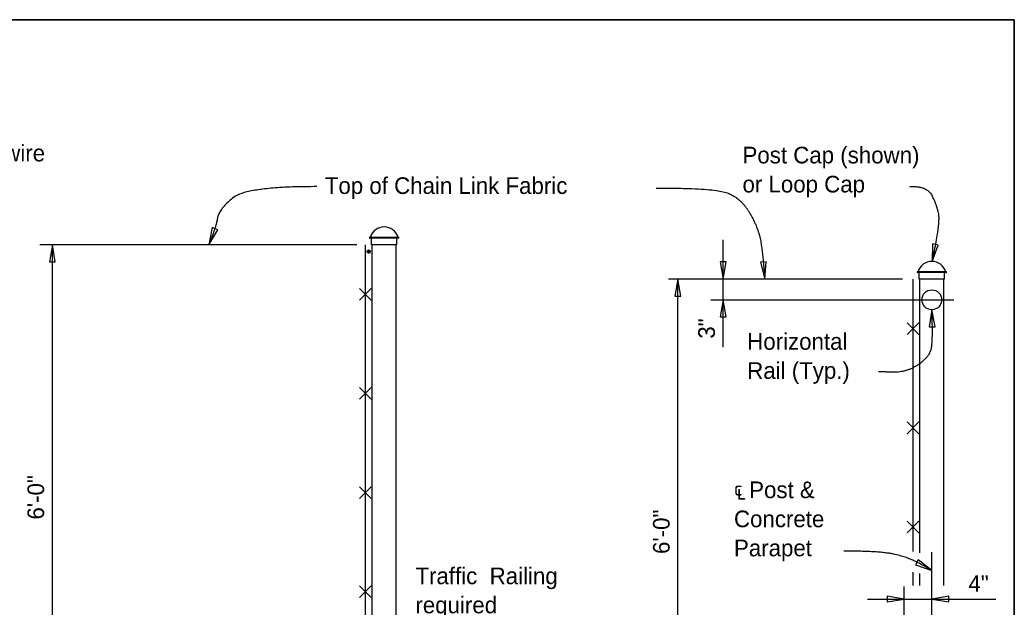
# Model space of a CAD drawing. Extents: x 0 to 41.1, y 0 to 25.9.
# Drawn here: x 29.01 to 41.05, y 18.84 to 25.95 of the extents above; entities that cross this region are included whole.
import ezdxf

# ---------------------------------------------------------------- set-up
doc = ezdxf.new("R2010")
doc.units = 0
for name, color, linetype in [('ActivePts-ConstElements', 7, 'Continuous'), ('CL_Major', 7, 'Continuous'), ('Dimension', 7, 'Continuous'), ('Miscellaneous', 7, 'Continuous'), ('Miscellaneous1', 7, 'Continuous'), ('SteelMisc', 7, 'Continuous'), ('TextStructures', 7, 'Continuous')]:
    doc.layers.add(name, color=color, linetype=linetype)

msp = doc.modelspace()

# ---------------------------------------------------------------- linework, layer by layer
at = {"layer": 'ActivePts-ConstElements'}
msp.add_lwpolyline([(0, 0), (41.051, 0), (41.051, 25.946), (0, 25.946)], close=True, dxfattribs=at)
msp.add_lwpolyline([(0, 0), (41.051, 0), (41.051, 25.946), (0, 25.946)], close=True, dxfattribs=at)
msp.add_lwpolyline([(0, 0), (41.051, 0), (41.051, 25.946), (0, 25.946)], close=True, dxfattribs=at)
at = {"layer": 'CL_Major'}
for p, q in [((37.378, 22.558), (40.319, 22.558)), ((40.054, 15.283), (40.054, 19.502))]:
    msp.add_line(p, q, dxfattribs=at)
at = {"layer": 'Dimension'}
for p, q in [((37.528, 21.984), (37.528, 23.282)), ((33.092, 23.225), (29.256, 23.225)), ((29.406, 14.558), (29.406, 23.225)), ((39.699, 22.808), (36.866, 22.808)), ((36.98, 14.578), (36.98, 22.808)), ((39.72, 16.978), (39.72, 19.086)), ((39.274, 18.936), (40.828, 18.936))]:
    msp.add_line(p, q, dxfattribs=at)
for points in [[(31.3, 23.225), (31.408, 23.406), (31.342, 23.432)], [(40.057, 23.023), (40.131, 23.22), (40.062, 23.234)], [(29.406, 23.225), (29.371, 23.016), (29.441, 23.016)], [(37.528, 22.808), (37.563, 23.016), (37.492, 23.016)], [(38.031, 22.808), (38.049, 23.018), (37.979, 23.013)], [(36.98, 22.808), (36.944, 22.6), (37.015, 22.6)], [(37.528, 22.558), (37.492, 22.35), (37.563, 22.35)], [(40.054, 22.438), (40.024, 22.229), (40.095, 22.231)], [(40.054, 19.28), (39.889, 19.412), (39.855, 19.35)], [(39.72, 18.936), (39.512, 18.971), (39.512, 18.901)], [(40.054, 18.936), (40.262, 18.901), (40.262, 18.971)]]:
    msp.add_lwpolyline(points, close=True, dxfattribs=at)
for points in [[(32.608, 23.928), (31.76, 23.928), (31.424, 23.657), (31.383, 23.422), (31.3, 23.225)], [(36.717, 23.911), (37.4, 23.911), (37.736, 23.799), (37.958, 23.427), (38.014, 23.066), (38.031, 22.808)], [(39.786, 23.927), (39.992, 23.942), (40.118, 23.698), (40.152, 23.473), (40.057, 23.023)], [(39.41, 21.689), (39.436, 21.689), (39.754, 21.683), (40.017, 21.86), (40.072, 22.038), (40.054, 22.438)], [(38.988, 19.52), (39.396, 19.52), (39.727, 19.457), (39.975, 19.335), (40.054, 19.28)]]:
    msp.add_open_spline(points, degree=2, dxfattribs=at)
at = {"layer": 'Miscellaneous'}
for p, q in [((33.265, 22.695), (33.124, 22.554)), ((33.124, 22.695), (33.265, 22.554)), ((39.895, 22.279), (39.754, 22.137)), ((39.754, 22.279), (39.895, 22.137)), ((33.265, 21.495), (33.124, 21.354)), ((33.124, 21.495), (33.265, 21.354)), ((39.895, 21.079), (39.754, 20.937)), ((39.754, 21.079), (39.895, 20.937)), ((33.265, 20.295), (33.124, 20.154)), ((33.124, 20.295), (33.265, 20.154)), ((39.895, 19.879), (39.754, 19.737)), ((39.754, 19.879), (39.895, 19.737)), ((33.265, 19.095), (33.124, 18.954)), ((33.124, 19.095), (33.265, 18.954))]:
    msp.add_line(p, q, dxfattribs=at)
for points in [[(33.195, 23.225), (33.195, 17.225)], [(39.825, 22.808), (39.825, 19.51)], [(39.825, 19.262), (39.825, 19.1)]]:
    msp.add_lwpolyline(points, dxfattribs=at)
at = {"layer": 'Miscellaneous1'}
msp.add_lwpolyline([(0, 25.946), (41.051, 25.946), (41.051, 0), (0, 0)], close=True, dxfattribs=at)
at = {"layer": 'SteelMisc'}
for p, q in [((33.251, 23.317), (33.596, 23.317)), ((33.596, 23.304), (33.251, 23.304)), ((33.27, 23.225), (33.27, 23.304)), ((33.578, 23.225), (33.578, 23.304)), ((33.195, 23.225), (33.195, 17.225)), ((33.578, 23.225), (33.27, 23.225)), ((33.278, 16.889), (33.278, 23.225)), ((33.57, 16.889), (33.57, 23.225)), ((39.881, 22.9), (40.226, 22.9)), ((40.226, 22.888), (39.881, 22.888)), ((39.9, 22.808), (39.9, 22.888)), ((40.208, 22.808), (40.208, 22.888)), ((40.208, 22.808), (39.9, 22.808)), ((39.908, 19.495), (39.908, 22.808)), ((40.2, 19.1), (40.2, 22.808)), ((39.908, 19.1), (39.908, 19.244))]:
    msp.add_line(p, q, dxfattribs=at)
for centre, radius in [((33.236, 23.141), 0.0197), ((33.236, 23.141), 0.0172), ((33.236, 23.141), 0.0147), ((33.236, 23.141), 0.0122), ((33.236, 23.141), 0.00975), ((33.236, 23.141), 0.00725), ((33.236, 23.141), 0.00475), ((33.236, 23.141), 0.00225), ((40.054, 22.558), 0.12)]:
    msp.add_circle(centre, radius, dxfattribs=at)
for centre, start, end in [((33.252, 23.31), 91.1647, 268.8353), ((33.596, 23.31), 271.1647, 88.8353), ((39.882, 22.894), 91.1647, 268.8353), ((40.226, 22.894), 271.1647, 88.8353)]:
    msp.add_arc(centre, 0.00613, start, end, dxfattribs=at)
for centre in [(33.424, 23.276), (40.054, 22.859)]:
    msp.add_ellipse(centre, major_axis=(0.171, 0), ratio=0.957868, start_param=0.252602, end_param=2.888574, dxfattribs=at)

# ---------------------------------------------------------------- texts
at = {"layer": 'Dimension'}
for s, p in [('No. 9 gage zinc coated tie wire ', (25.632, 24.233)), ('Post Cap (shown) ', (37.762, 24.209)), ('or Loop Cap', (37.762, 23.857)), ('Horizontal', (37.819, 21.953)), ('Rail (Typ.)', (37.819, 21.601)), ('℄ Post &', (37.659, 20.157)), ('Concrete', (37.659, 19.805)), ('Parapet', (37.659, 19.453)), ('Traffic  Railing', (33.802, 19.115)), ('required', (33.802, 18.763))]:
    msp.add_text(s, height=0.2016, dxfattribs=at).set_placement(p)
at = {"layer": 'TextStructures'}
for s, p in [('Top of Chain Link Fabric', (32.705, 23.839)), ('4"', (40.497, 19.023))]:
    msp.add_text(s, height=0.2016, dxfattribs=at).set_placement(p)
for s, p in [('3"', (37.428, 22.087)), ('6\'-0"', (29.306, 19.898)), ('6\'-0"', (36.88, 19.481))]:
    msp.add_text(s, height=0.2016, rotation=90, dxfattribs=at).set_placement(p)

doc.saveas('drawing.dxf')
